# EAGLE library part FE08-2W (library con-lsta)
FEMALE HEADER
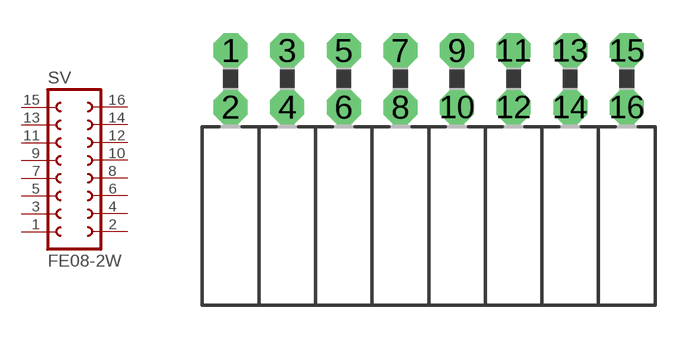
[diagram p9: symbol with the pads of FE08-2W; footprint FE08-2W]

Designator prefix SV

## FE08-2W (OC_FARNELL: unknown; OC_NEWARK: unknown)  [FE08-2W]
1  1  pas
2  2  pas
3  3  pas
4  4  pas
5  5  pas
6  6  pas
7  7  pas
8  8  pas
9  9  pas
10  10  pas
11  11  pas
12  12  pas
13  13  pas
14  14  pas
15  15  pas
16  16  pas

## Footprint FE08-2W (pad centres in mm)
FEMALE HEADER
drill 1.016 octagon: 1 -8.89,1.27; 2 -8.89,-1.27; 3 -6.35,1.27; 4 -6.35,-1.27; 5 -3.81,1.27; 6 -3.81,-1.27; 7 -1.27,1.27; 8 -1.27,-1.27; 9 1.27,1.27; 10 1.27,-1.27; 11 3.81,1.27; 12 3.81,-1.27; 13 6.35,1.27; 14 6.35,-1.27; 15 8.89,1.27; 16 8.89,-1.27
